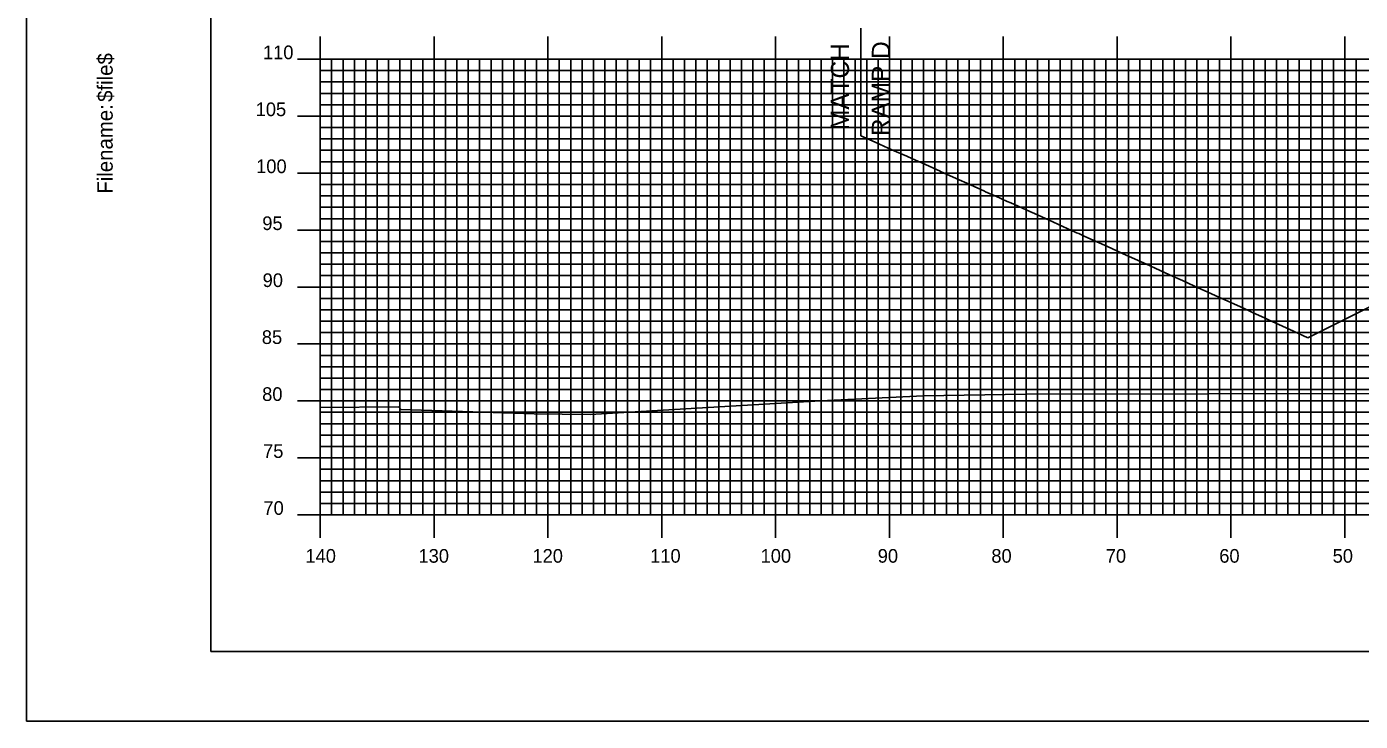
# Model space of a CAD drawing. Extents: x 1756282 to 1756625, y 442591 to 442811.
# Drawn here: x 1756281.8 to 1756398.9, y 442590.5 to 442651.5 of the extents above; entities that cross this region are included whole.
import ezdxf

# ---------------------------------------------------------------- set-up
doc = ezdxf.new("R2010")
doc.units = 0
for name, color, linetype in [('ANNOTATION', 7, 'Continuous'), ('BORDER', 7, 'Continuous'), ('D_Roadway_Centerline', 7, 'Continuous'), ('D_Roadway_SlopeLines', 7, 'Continuous'), ('D_Roadway_SubGrade', 7, 'Continuous'), ('H_V ANNOTATION', 7, 'Continuous'), ('MAJOR', 7, 'Continuous'), ('MINOR', 7, 'Continuous'), ('PLOT BOUNDARY', 7, 'Continuous'), ('S_Roadway_Centerline', 7, 'Continuous')]:
    doc.layers.add(name, color=color, linetype=linetype)

msp = doc.modelspace()

# ---------------------------------------------------------------- linework, layer by layer
at = {"layer": 'BORDER'}
msp.add_lwpolyline([(1756297.97, 442596.67), (1756617.97, 442596.67), (1756617.97, 442806.67), (1756297.97, 442806.67)], close=True, dxfattribs=at)
at = {"layer": 'D_Roadway_Centerline'}
for points in [[(1756355.07, 442641.95), (1756356.31, 442641.39), (1756357.47, 442640.87), (1756358.2, 442640.55), (1756359.1, 442640.15), (1756359.6, 442639.92), (1756359.73, 442639.86), (1756360.11, 442639.7), (1756360.4, 442639.56), (1756361.38, 442639.12), (1756362.03, 442638.83), (1756362.06, 442638.82), (1756363.97, 442637.96), (1756364.09, 442637.91), (1756365.93, 442637.08), (1756366.02, 442637.04), (1756366.78, 442636.7), (1756366.92, 442636.64), (1756367.91, 442636.19), (1756368.22, 442636.05), (1756369.9, 442635.3), (1756370.31, 442635.11), (1756371.91, 442634.39), (1756372.42, 442634.16), (1756373.94, 442633.47), (1756374.01, 442633.44), (1756374.19, 442633.36), (1756374.74, 442633.11), (1756375.99, 442632.55), (1756376.71, 442632.22), (1756378.05, 442631.62), (1756378.89, 442631.24), (1756380.14, 442630.67), (1756380.91, 442630.32), (1756381.85, 442629.89), (1756382.04, 442629.81), (1756382.24, 442629.72), (1756383.31, 442629.23), (1756384.36, 442628.75), (1756385.55, 442628.21), (1756386.51, 442627.78), (1756387.82, 442627.18), (1756388.67, 442626.8), (1756389.39, 442626.47), (1756389.78, 442626.29), (1756390.5, 442625.96), (1756390.86, 442625.8), (1756392.43, 442625.08), (1756393.06, 442624.79), (1756394.32, 442624.22)], [(1756394.32, 442624.22), (1756419.82, 442636.97)]]:
    msp.add_lwpolyline(points, dxfattribs=at)
at = {"layer": 'D_Roadway_SlopeLines'}
msp.add_lwpolyline([(1756424.57, 442639.35), (1756394.32, 442624.22)], dxfattribs=at)
at = {"layer": 'D_Roadway_SubGrade'}
msp.add_line((1756355.07, 442651.4), (1756355.07, 442641.95), dxfattribs=at)
at = {"layer": 'MAJOR'}
for p, q in [((1756307.57, 442650.67), (1756307.57, 442648.67)), ((1756317.57, 442650.67), (1756317.57, 442648.67)), ((1756327.57, 442650.67), (1756327.57, 442648.67)), ((1756337.57, 442650.67), (1756337.57, 442648.67)), ((1756347.57, 442650.67), (1756347.57, 442648.67)), ((1756357.57, 442650.67), (1756357.57, 442648.67)), ((1756367.57, 442650.67), (1756367.57, 442648.67)), ((1756377.57, 442650.67), (1756377.57, 442648.67)), ((1756387.57, 442650.67), (1756387.57, 442648.67)), ((1756397.57, 442650.67), (1756397.57, 442648.67)), ((1756305.57, 442648.67), (1756307.57, 442648.67)), ((1756307.57, 442648.67), (1756587.57, 442648.67)), ((1756307.57, 442608.67), (1756307.57, 442648.67)), ((1756307.57, 442608.67), (1756307.57, 442648.67)), ((1756307.57, 442648.67), (1756587.57, 442648.67)), ((1756317.57, 442608.67), (1756317.57, 442648.67)), ((1756327.57, 442608.67), (1756327.57, 442648.67)), ((1756337.57, 442608.67), (1756337.57, 442648.67)), ((1756347.57, 442608.67), (1756347.57, 442648.67)), ((1756357.57, 442608.67), (1756357.57, 442648.67)), ((1756367.57, 442608.67), (1756367.57, 442648.67)), ((1756377.57, 442608.67), (1756377.57, 442648.67)), ((1756387.57, 442608.67), (1756387.57, 442648.67)), ((1756397.57, 442608.67), (1756397.57, 442648.67)), ((1756305.57, 442643.67), (1756307.57, 442643.67)), ((1756307.57, 442643.67), (1756587.57, 442643.67)), ((1756305.57, 442638.67), (1756307.57, 442638.67)), ((1756307.57, 442638.67), (1756587.57, 442638.67)), ((1756305.57, 442633.67), (1756307.57, 442633.67)), ((1756307.57, 442633.67), (1756587.57, 442633.67)), ((1756305.57, 442628.67), (1756307.57, 442628.67)), ((1756307.57, 442628.67), (1756587.57, 442628.67)), ((1756305.57, 442623.67), (1756307.57, 442623.67)), ((1756307.57, 442623.67), (1756587.57, 442623.67)), ((1756305.57, 442618.67), (1756307.57, 442618.67)), ((1756307.57, 442618.67), (1756587.57, 442618.67)), ((1756305.57, 442613.67), (1756307.57, 442613.67)), ((1756307.57, 442613.67), (1756587.57, 442613.67)), ((1756305.57, 442608.67), (1756307.57, 442608.67)), ((1756307.57, 442608.67), (1756587.57, 442608.67)), ((1756307.57, 442608.67), (1756587.57, 442608.67)), ((1756307.57, 442606.66), (1756307.57, 442608.67)), ((1756317.57, 442606.66), (1756317.57, 442608.67)), ((1756327.57, 442606.66), (1756327.57, 442608.67)), ((1756337.57, 442606.66), (1756337.57, 442608.67)), ((1756347.57, 442606.66), (1756347.57, 442608.67)), ((1756357.57, 442606.66), (1756357.57, 442608.67)), ((1756367.57, 442606.66), (1756367.57, 442608.67)), ((1756377.57, 442606.66), (1756377.57, 442608.67)), ((1756387.57, 442606.66), (1756387.57, 442608.67)), ((1756397.57, 442606.66), (1756397.57, 442608.67))]:
    msp.add_line(p, q, dxfattribs=at)
at = {"layer": 'MINOR'}
for p, q in [((1756308.57, 442608.67), (1756308.57, 442648.67)), ((1756309.57, 442608.67), (1756309.57, 442648.67)), ((1756310.57, 442608.67), (1756310.57, 442648.67)), ((1756311.57, 442608.67), (1756311.57, 442648.67)), ((1756312.57, 442608.67), (1756312.57, 442648.67)), ((1756313.57, 442608.67), (1756313.57, 442648.67)), ((1756314.57, 442608.67), (1756314.57, 442648.67)), ((1756315.57, 442608.67), (1756315.57, 442648.67)), ((1756316.57, 442608.67), (1756316.57, 442648.67)), ((1756318.57, 442608.67), (1756318.57, 442648.67)), ((1756319.57, 442608.67), (1756319.57, 442648.67)), ((1756320.57, 442608.67), (1756320.57, 442648.67)), ((1756321.57, 442608.67), (1756321.57, 442648.67)), ((1756322.57, 442608.67), (1756322.57, 442648.67)), ((1756323.57, 442608.67), (1756323.57, 442648.67)), ((1756324.57, 442608.67), (1756324.57, 442648.67)), ((1756325.57, 442608.67), (1756325.57, 442648.67)), ((1756326.57, 442608.67), (1756326.57, 442648.67)), ((1756328.57, 442608.67), (1756328.57, 442648.67)), ((1756329.57, 442608.67), (1756329.57, 442648.67)), ((1756330.57, 442608.67), (1756330.57, 442648.67)), ((1756331.57, 442608.67), (1756331.57, 442648.67)), ((1756332.57, 442608.67), (1756332.57, 442648.67)), ((1756333.57, 442608.67), (1756333.57, 442648.67)), ((1756334.57, 442608.67), (1756334.57, 442648.67)), ((1756335.57, 442608.67), (1756335.57, 442648.67)), ((1756336.57, 442608.67), (1756336.57, 442648.67)), ((1756338.57, 442608.67), (1756338.57, 442648.67)), ((1756339.57, 442608.67), (1756339.57, 442648.67)), ((1756340.57, 442608.67), (1756340.57, 442648.67)), ((1756341.57, 442608.67), (1756341.57, 442648.67)), ((1756342.57, 442608.67), (1756342.57, 442648.67)), ((1756343.57, 442608.67), (1756343.57, 442648.67)), ((1756344.57, 442608.67), (1756344.57, 442648.67)), ((1756345.57, 442608.67), (1756345.57, 442648.67)), ((1756346.57, 442608.67), (1756346.57, 442648.67)), ((1756348.57, 442608.67), (1756348.57, 442648.67)), ((1756349.57, 442608.67), (1756349.57, 442648.67)), ((1756350.57, 442608.67), (1756350.57, 442648.67)), ((1756351.57, 442608.67), (1756351.57, 442648.67)), ((1756352.57, 442608.67), (1756352.57, 442648.67)), ((1756353.57, 442608.67), (1756353.57, 442648.67)), ((1756354.57, 442608.67), (1756354.57, 442648.67)), ((1756355.57, 442608.67), (1756355.57, 442648.67)), ((1756356.57, 442608.67), (1756356.57, 442648.67)), ((1756358.57, 442608.67), (1756358.57, 442648.67)), ((1756359.57, 442608.67), (1756359.57, 442648.67)), ((1756360.57, 442608.67), (1756360.57, 442648.67)), ((1756361.57, 442608.67), (1756361.57, 442648.67)), ((1756362.57, 442608.67), (1756362.57, 442648.67)), ((1756363.57, 442608.67), (1756363.57, 442648.67)), ((1756364.57, 442608.67), (1756364.57, 442648.67)), ((1756365.57, 442608.67), (1756365.57, 442648.67)), ((1756366.57, 442608.67), (1756366.57, 442648.67)), ((1756368.57, 442608.67), (1756368.57, 442648.67)), ((1756369.57, 442608.67), (1756369.57, 442648.67)), ((1756370.57, 442608.67), (1756370.57, 442648.67)), ((1756371.57, 442608.67), (1756371.57, 442648.67)), ((1756372.57, 442608.67), (1756372.57, 442648.67)), ((1756373.57, 442608.67), (1756373.57, 442648.67)), ((1756374.57, 442608.67), (1756374.57, 442648.67)), ((1756375.57, 442608.67), (1756375.57, 442648.67)), ((1756376.57, 442608.67), (1756376.57, 442648.67)), ((1756378.57, 442608.67), (1756378.57, 442648.67)), ((1756379.57, 442608.67), (1756379.57, 442648.67)), ((1756380.57, 442608.67), (1756380.57, 442648.67)), ((1756381.57, 442608.67), (1756381.57, 442648.67)), ((1756382.57, 442608.67), (1756382.57, 442648.67)), ((1756383.57, 442608.67), (1756383.57, 442648.67)), ((1756384.57, 442608.67), (1756384.57, 442648.67)), ((1756385.57, 442608.67), (1756385.57, 442648.67)), ((1756386.57, 442608.67), (1756386.57, 442648.67)), ((1756388.57, 442608.67), (1756388.57, 442648.67)), ((1756389.57, 442608.67), (1756389.57, 442648.67)), ((1756390.57, 442608.67), (1756390.57, 442648.67)), ((1756391.57, 442608.67), (1756391.57, 442648.67)), ((1756392.57, 442608.67), (1756392.57, 442648.67)), ((1756393.57, 442608.67), (1756393.57, 442648.67)), ((1756394.57, 442608.67), (1756394.57, 442648.67)), ((1756395.57, 442608.67), (1756395.57, 442648.67)), ((1756396.57, 442608.67), (1756396.57, 442648.67)), ((1756398.57, 442608.67), (1756398.57, 442648.67)), ((1756307.57, 442647.67), (1756587.57, 442647.67)), ((1756307.57, 442647.67), (1756309.57, 442647.67)), ((1756307.57, 442646.67), (1756587.57, 442646.67)), ((1756307.57, 442646.67), (1756309.57, 442646.67)), ((1756307.57, 442645.67), (1756587.57, 442645.67)), ((1756307.57, 442645.67), (1756309.57, 442645.67)), ((1756307.57, 442644.67), (1756587.57, 442644.67)), ((1756307.57, 442644.67), (1756309.57, 442644.67)), ((1756307.57, 442642.67), (1756587.57, 442642.67)), ((1756307.57, 442642.67), (1756309.57, 442642.67)), ((1756307.57, 442641.67), (1756587.57, 442641.67)), ((1756307.57, 442641.67), (1756309.57, 442641.67)), ((1756307.57, 442640.67), (1756587.57, 442640.67)), ((1756307.57, 442640.67), (1756309.57, 442640.67)), ((1756307.57, 442639.67), (1756587.57, 442639.67)), ((1756307.57, 442639.67), (1756309.57, 442639.67)), ((1756307.57, 442637.67), (1756587.57, 442637.67)), ((1756307.57, 442637.67), (1756309.57, 442637.67)), ((1756307.57, 442636.67), (1756587.57, 442636.67)), ((1756307.57, 442636.67), (1756309.57, 442636.67)), ((1756307.57, 442635.67), (1756587.57, 442635.67)), ((1756307.57, 442635.67), (1756309.57, 442635.67)), ((1756307.57, 442634.67), (1756587.57, 442634.67)), ((1756307.57, 442634.67), (1756309.57, 442634.67)), ((1756307.57, 442632.67), (1756587.57, 442632.67)), ((1756307.57, 442632.67), (1756309.57, 442632.67)), ((1756307.57, 442631.67), (1756587.57, 442631.67)), ((1756307.57, 442631.67), (1756309.57, 442631.67)), ((1756307.57, 442630.67), (1756587.57, 442630.67)), ((1756307.57, 442630.67), (1756309.57, 442630.67)), ((1756307.57, 442629.67), (1756587.57, 442629.67)), ((1756307.57, 442629.67), (1756309.57, 442629.67)), ((1756307.57, 442627.67), (1756587.57, 442627.67)), ((1756307.57, 442627.67), (1756309.57, 442627.67)), ((1756307.57, 442626.67), (1756587.57, 442626.67)), ((1756307.57, 442626.67), (1756309.57, 442626.67)), ((1756307.57, 442625.67), (1756587.57, 442625.67)), ((1756307.57, 442625.67), (1756309.57, 442625.67)), ((1756307.57, 442624.67), (1756587.57, 442624.67)), ((1756307.57, 442624.67), (1756309.57, 442624.67)), ((1756307.57, 442622.67), (1756587.57, 442622.67)), ((1756307.57, 442622.67), (1756309.57, 442622.67)), ((1756307.57, 442621.67), (1756587.57, 442621.67)), ((1756307.57, 442621.67), (1756309.57, 442621.67)), ((1756307.57, 442620.67), (1756587.57, 442620.67)), ((1756307.57, 442620.67), (1756309.57, 442620.67)), ((1756307.57, 442619.67), (1756587.57, 442619.67)), ((1756307.57, 442619.67), (1756309.57, 442619.67)), ((1756307.57, 442617.67), (1756587.57, 442617.67)), ((1756307.57, 442617.67), (1756309.57, 442617.67)), ((1756307.57, 442616.67), (1756587.57, 442616.67)), ((1756307.57, 442616.67), (1756309.57, 442616.67)), ((1756307.57, 442615.67), (1756587.57, 442615.67)), ((1756307.57, 442615.67), (1756309.57, 442615.67)), ((1756307.57, 442614.67), (1756587.57, 442614.67)), ((1756307.57, 442614.67), (1756309.57, 442614.67)), ((1756307.57, 442612.67), (1756587.57, 442612.67)), ((1756307.57, 442612.67), (1756309.57, 442612.67)), ((1756307.57, 442611.67), (1756587.57, 442611.67)), ((1756307.57, 442611.67), (1756309.57, 442611.67)), ((1756307.57, 442610.67), (1756587.57, 442610.67)), ((1756307.57, 442610.67), (1756309.57, 442610.67)), ((1756307.57, 442609.67), (1756587.57, 442609.67)), ((1756307.57, 442609.67), (1756309.57, 442609.67))]:
    msp.add_line(p, q, dxfattribs=at)
at = {"layer": 'PLOT BOUNDARY'}
msp.add_lwpolyline([(1756281.78, 442590.55), (1756621.78, 442590.55), (1756621.78, 442810.55), (1756281.78, 442810.55)], close=True, dxfattribs=at)
at = {"layer": 'S_Roadway_Centerline'}
msp.add_lwpolyline([(1756307.57, 442618.08), (1756314.44, 442618.16), (1756314.67, 442617.91), (1756326.37, 442617.54), (1756331.28, 442617.49), (1756351.52, 442618.67), (1756360.56, 442619.11), (1756369.53, 442619.26), (1756401.49, 442619.32), (1756415.22, 442619.96), (1756421.47, 442620.05), (1756445.66, 442619.4), (1756471.4, 442619.4), (1756485.64, 442619.61), (1756486.6, 442619.72), (1756492.85, 442619.49), (1756514.56, 442620.04), (1756517.59, 442619.61), (1756534.91, 442619.98), (1756554.07, 442620.19), (1756568.96, 442620.31), (1756579.7, 442620.36), (1756585.04, 442620.35), (1756587.57, 442620.19)], dxfattribs=at)

# ---------------------------------------------------------------- texts
at = {"layer": 'ANNOTATION'}
for s, p in [('MATCH', (1756354.02, 442642.46)), ('RAMP D', (1756357.62, 442641.92))]:
    msp.add_text(s, height=1.6, rotation=90, dxfattribs=at).set_placement(p)
at = {"layer": 'BORDER'}
for s, p in [('$file$', (1756289.34, 442644.92)), ('$file$', (1756289.34, 442644.92)), ('Filename:', (1756289.34, 442636.86)), ('Filename:', (1756289.34, 442636.86))]:
    msp.add_text(s, height=1.339, rotation=90, dxfattribs=at).set_placement(p)
at = {"layer": 'H_V ANNOTATION'}
for s, p in [('110', (1756302.54, 442648.67)), ('105', (1756301.9, 442643.67)), ('100', (1756301.94, 442638.67)), ('95', (1756302.48, 442633.67)), ('90', (1756302.51, 442628.67)), ('85', (1756302.44, 442623.67)), ('80', (1756302.47, 442618.67)), ('75', (1756302.55, 442613.67)), ('70', (1756302.58, 442608.67)), ('140', (1756306.27, 442604.47)), ('130', (1756316.2, 442604.47)), ('120', (1756326.21, 442604.47)), ('110', (1756336.55, 442604.47)), ('100', (1756346.25, 442604.47)), ('90', (1756356.54, 442604.47)), ('80', (1756366.52, 442604.47)), ('70', (1756376.57, 442604.47)), ('60', (1756386.54, 442604.47)), ('50', (1756396.5, 442604.47))]:
    msp.add_text(s, height=1.2, dxfattribs=at).set_placement(p)
at = {"layer": 'MAJOR'}
msp.add_text('-', height=0.012, dxfattribs=at).set_placement((1756307.56, 442608.67))

doc.saveas('drawing.dxf')
